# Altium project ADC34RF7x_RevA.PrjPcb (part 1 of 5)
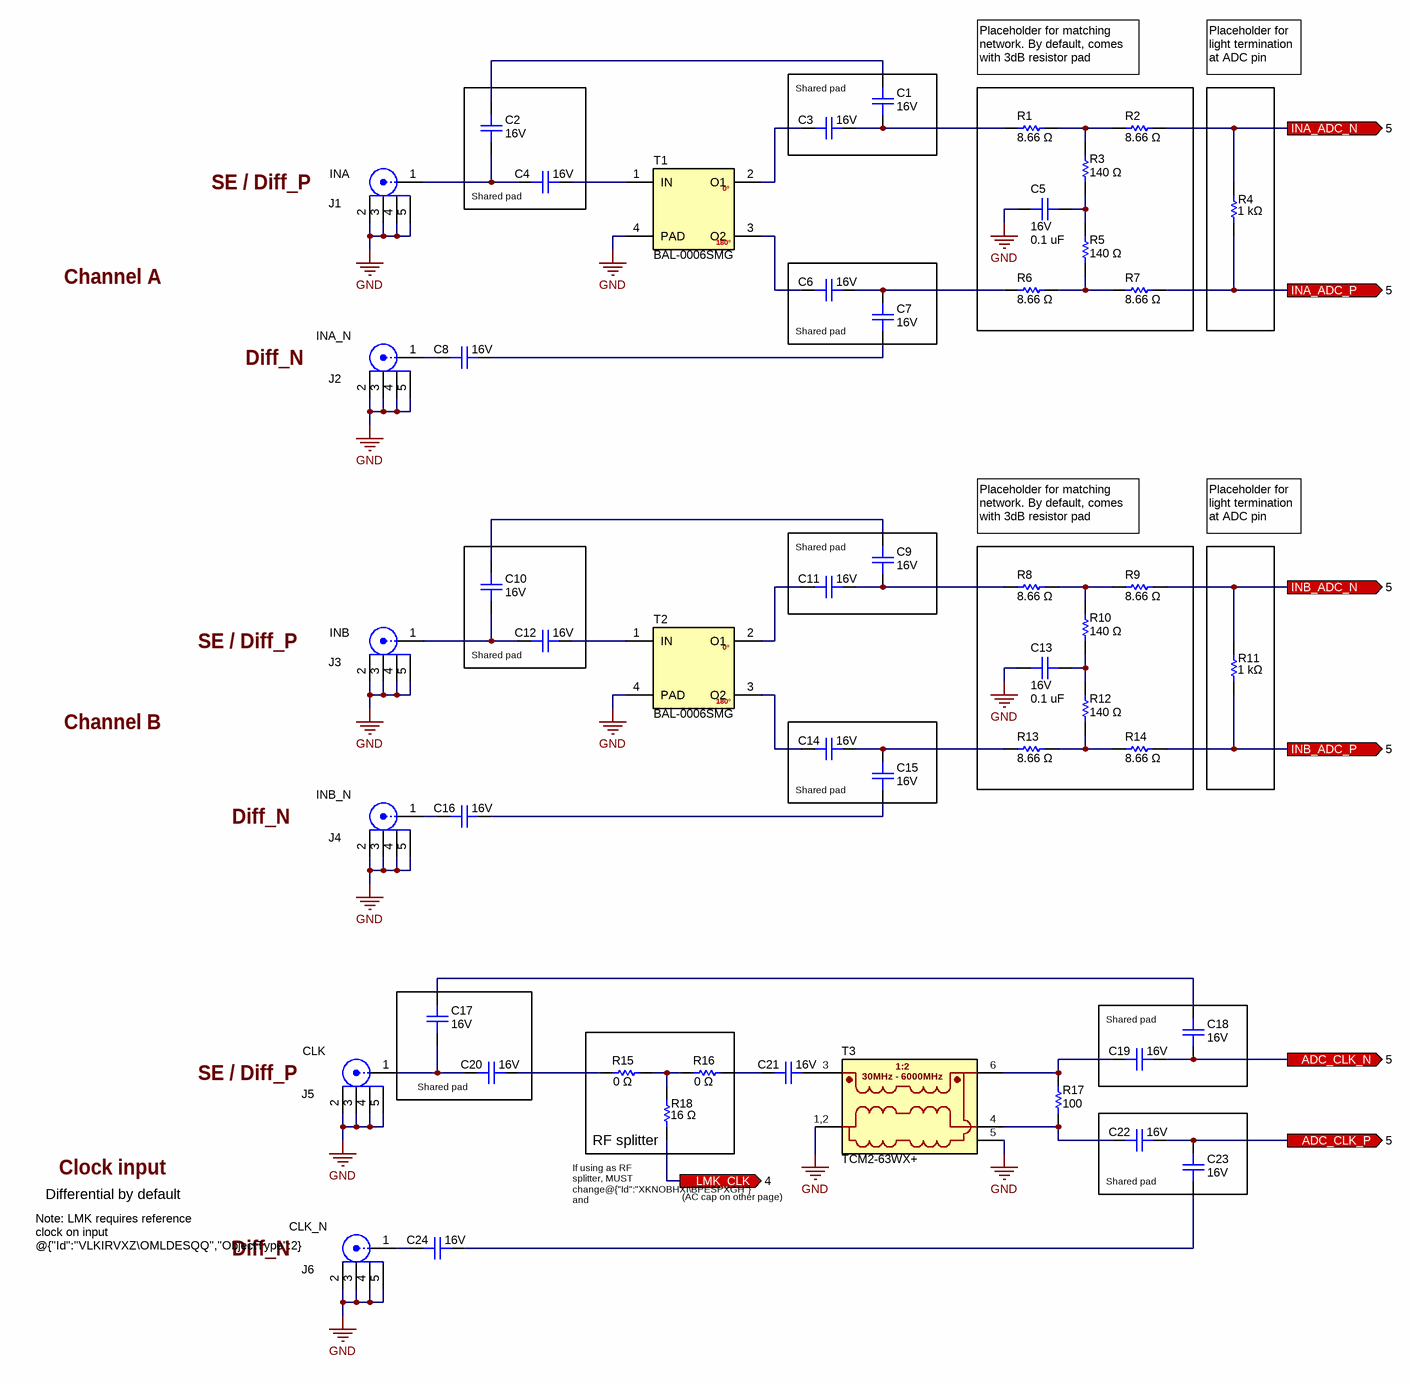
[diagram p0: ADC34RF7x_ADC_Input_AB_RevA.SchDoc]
TID: Not For Public Release; TechSupport: http://www.ti.com/support; SCH_Rev: A; PRJ_Title: ADC34RF7xEVM; PRJ_Number: -; PRJ_Engineer: CW; PRJ_Customer: Not For Public Release; PCB_Rev: A; PCB_Layout: CW/GR; EVM_Orderable: Not For Public Release; Drawn_By: CW; CopyrightYear: 2024; BrdNum: DC311
20 sheets, 672 parts. Net scope: flat (ports and power ports of the same name join across sheets).
Board file: ADC34RF7x_REV_A.PcbDoc
Sheets:
  ADC34RF7x_BlockDiagram_RevA.SchDoc
  ADC34RF7x_ADC_Input_AB_RevA.SchDoc
  ADC34RF7x_ADC_Input_CD_RevA.SchDoc
  ADC34RF7x_LMK_RevA.SchDoc
  ADC34RF7x_ADC_Dig_RevA.SchDoc
  ADC34RF7x_ADC_Power_RevA.SchDoc
  ADC34RF7x_FMC_RevA.SchDoc
  ADC34RF7x_USB_RevA.SchDoc
  ADC34RF7x_LVL_Shft_RevA.SchDoc
  ADC34RF7x_MUX_RevA.SchDoc
  ADC34RF7x_SYSREF_FPGA_MUX_RevA.SchDoc
  ADC34RF7x_Power1_RevA.SchDoc
  ADC34RF7x_Power_Sequencer.SchDoc
  ADC34RF7x_Power2_RevA.SchDoc
  ADC34RF7x_Power3_RevA.SchDoc
  ADC34RF7x_Power4_RevA.SchDoc
  ADC34RF7x_I2C_Shunts_Margining.SchDoc
  ADC34RF7x_uFit_Power.SchDoc
  ADC34RF7x_Misc_RevA.SchDoc
  ADC34RF7x_Revision History.SchDoc

## Sheet ADC34RF7x_BlockDiagram_RevA.SchDoc: Block Diagram
size 431 x 279 mm; Date: Not shown in title block; ApprovedBy: Not shown in title block; CheckedBy: Not shown in title block; Author: Not shown in title block; CompanyName: Not shown in title block; DrawnBy: CW; Engineer: Not shown in title block; Organization: Not shown in title block; Address1: Not shown in title block; Address2: Not shown in title block; Address3: Not shown in title block; Address4: Not shown in title block; DocumentNumber: 1; Revision: Use project parameter SCH_Rev; SheetNumber: 1; SheetTotal: 19; PageSetup: Record=PageOptions¦CenterHorizontal=True¦CenterVertical=True¦PrintScale=1.00¦XCorrection=1.00¦YCorrection=1.00¦PrintKind=0¦BorderSize=5000000¦LeftOffset=0¦BottomOffset=0¦Orientation=2¦PaperLength=1000¦PaperWidth=1000¦Scale=100¦PaperSource=15¦PrintQuality=600¦MediaType=1¦DitherType=10¦PaperKind=Letter¦PrintScaleMode=1

## Sheet ADC34RF7x_ADC_Input_AB_RevA.SchDoc: ADC EVM RF Input
size 431 x 279 mm; Date: Not shown in title block; ApprovedBy: Not shown in title block; CheckedBy: Not shown in title block; Author: Not shown in title block; CompanyName: Not shown in title block; DrawnBy: CW; Engineer: Not shown in title block; Organization: Not shown in title block; Address1: Not shown in title block; Address2: Not shown in title block; Address3: Not shown in title block; Address4: Not shown in title block; DocumentNumber: 2; Revision: Use project parameter SCH_Rev; SheetNumber: 2; SheetTotal: 19; PageSetup: Record=PageOptions¦CenterHorizontal=True¦CenterVertical=True¦PrintScale=1.00¦XCorrection=1.00¦YCorrection=1.00¦PrintKind=0¦BorderSize=5000000¦LeftOffset=0¦BottomOffset=0¦Orientation=2¦PaperLength=1000¦PaperWidth=1000¦Scale=100¦PaperSource=15¦PrintQuality=600¦MediaType=1¦DitherType=10¦PaperKind=Letter¦PrintScaleMode=1

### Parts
C1  Voltage - Rated: 16V  [0201_cap]  (hidden comment: 0201BB104KW160)
C2  Voltage - Rated: 16V  [0201_cap]  (hidden comment: 0201BB104KW160)
C3  Voltage - Rated: 16V  [0201_cap]  (hidden comment: 0201BB104KW160)
C4  Voltage - Rated: 16V  [0201_cap]  (hidden comment: 0201BB104KW160)
C5  value 0.1 uF  Voltage - Rated: 16V  [0201_cap]  (hidden comment: GRM033Z71C104KE14D)
C6  Voltage - Rated: 16V  [0201_cap]  (hidden comment: 0201BB104KW160)
C7  Voltage - Rated: 16V  [0201_cap]  (hidden comment: 0201BB104KW160)
C8  Voltage - Rated: 16V  [0201_cap]  (hidden comment: 0201BB104KW160)
C9  Voltage - Rated: 16V  [0201_cap]  (hidden comment: 0201BB104KW160)
C10  Voltage - Rated: 16V  [0201_cap]  (hidden comment: 0201BB104KW160)
C11  Voltage - Rated: 16V  [0201_cap]  (hidden comment: 0201BB104KW160)
C12  Voltage - Rated: 16V  [0201_cap]  (hidden comment: 0201BB104KW160)
C13  value 0.1 uF  Voltage - Rated: 16V  [0201_cap]  (hidden comment: GRM033Z71C104KE14D)
C14  Voltage - Rated: 16V  [0201_cap]  (hidden comment: 0201BB104KW160)
C15  Voltage - Rated: 16V  [0201_cap]  (hidden comment: 0201BB104KW160)
C16  Voltage - Rated: 16V  [0201_cap]  (hidden comment: 0201BB104KW160)
C17  Voltage - Rated: 16V  [0201_cap]  (hidden comment: 0201BB104KW160)
C18  Voltage - Rated: 16V  [0201_cap]  (hidden comment: 0201BB104KW160)
C19  Voltage - Rated: 16V  [0201_cap]  (hidden comment: 0201BB104KW160)
C20  Voltage - Rated: 16V  [0201_cap]  (hidden comment: 0201BB104KW160)
C21  Voltage - Rated: 16V  [0201_cap]  (hidden comment: 0201BB104KW160)
C22  Voltage - Rated: 16V  [0201_cap]  (hidden comment: 0201BB104KW160)
C23  Voltage - Rated: 16V  [0201_cap]  (hidden comment: 0201BB104KW160)
C24  Voltage - Rated: 16V  [0201_cap]  (hidden comment: 0201BB104KW160)
J1  Text1: INA  [FP-132134-15_CONN_SMA_JACK-MFG]  (hidden comment: 132134-15)
J2  Text1: INA_N  [FP-132134-15_CONN_SMA_JACK-MFG]  (hidden comment: 132134-15)
J3  Text1: INB  [FP-132134-15_CONN_SMA_JACK-MFG]  (hidden comment: 132134-15)
J4  Text1: INB_N  [FP-132134-15_CONN_SMA_JACK-MFG]  (hidden comment: 132134-15)
J5  Text1: CLK  [FP-132134-15_CONN_SMA_JACK-MFG]  (hidden comment: 132134-15)
J6  Text1: CLK_N  [FP-132134-15_CONN_SMA_JACK-MFG]  (hidden comment: 132134-15)
R1  value 8.66 Ω  [0201]  (hidden comment: RC0201FR-078R66L)
R2  value 8.66 Ω  [0201]  (hidden comment: RC0201FR-078R66L)
R3  value 140 Ω  [0201]  (hidden comment: ERJ-1GNF1400C)
R4  value 1 kΩ  [0201]  (hidden comment: ERJ-1GNF1001C)
R5  value 140 Ω  [0201]  (hidden comment: ERJ-1GNF1400C)
R6  value 8.66 Ω  [0201]  (hidden comment: RC0201FR-078R66L)
R7  value 8.66 Ω  [0201]  (hidden comment: RC0201FR-078R66L)
R8  value 8.66 Ω  [0201]  (hidden comment: RC0201FR-078R66L)
R9  value 8.66 Ω  [0201]  (hidden comment: RC0201FR-078R66L)
R10  value 140 Ω  [0201]  (hidden comment: ERJ-1GNF1400C)
R11  value 1 kΩ  [0201]  (hidden comment: ERJ-1GNF1001C)
R12  value 140 Ω  [0201]  (hidden comment: ERJ-1GNF1400C)
R13  value 8.66 Ω  [0201]  (hidden comment: RC0201FR-078R66L)
R14  value 8.66 Ω  [0201]  (hidden comment: RC0201FR-078R66L)
R15  value 0 Ω  [0201]  (hidden comment: ERJ-1GN0R00C)
R16  value 0 Ω  [0201]  (hidden comment: ERJ-1GN0R00C)
R17  ValueDisplayed: 100  [0201L]  (hidden comment: RC0201FS-7D100RL)
R18  value 16 Ω  [0201]  (hidden comment: ERJ-1GNF16R0C)
T1  BAL-0006SMG  [Marki_BAL-000xSMG]
T2  BAL-0006SMG  [Marki_BAL-000xSMG]
T3  TCM2-63WX+  [DB1627 - Vias 1,2,5]

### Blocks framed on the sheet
RF splitter: R15 R16 R18

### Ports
ADC_CLK_N (out, see 5), ADC_CLK_P (out, see 5), INA_ADC_N (out, see 5), INA_ADC_P (out, see 5), INB_ADC_N (out, see 5), INB_ADC_P (out, see 5), LMK_CLK (out, see 4)

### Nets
GND: C5.1 C13.1 J1.2 J1.3 J1.4 J1.5 J2.2 J2.3 J2.4 J2.5 J3.2 J3.3 J3.4 J3.5 J4.2 J4.3 J4.4 J4.5 J5.2 J5.3 J5.4 J5.5 J6.2 J6.3 J6.4 J6.5 T1.4(PAD) T2.4(PAD) T3.1,2(Primary) T3.5(NC)
ADC_CLK_N: C18.2 C19.2 ; port ADC_CLK_N
ADC_CLK_P: C22.2 C23.1 ; port ADC_CLK_P
INA_ADC_N: R2.2 R4.2 ; port INA_ADC_N
INA_ADC_P: R4.1 R7.2 ; port INA_ADC_P
INB_ADC_N: R9.2 R11.2 ; port INB_ADC_N
INB_ADC_P: R11.1 R14.2 ; port INB_ADC_P
LMK_CLK: R18.1 ; port LMK_CLK
NetC1_1: C1.1 C2.1
NetC1_2: C1.2 C3.2 R1.1
NetC2_2: C2.2 C4.1 J1.1
NetC3_1: C3.1 T1.2(O1)
NetC4_2: C4.2 T1.1(IN)
NetC5_2: C5.2 R3.1 R5.2
NetC6_1: C6.1 T1.3(O2)
NetC6_2: C6.2 C7.1 R6.1
NetC7_2: C7.2 C8.2
NetC8_1: C8.1 J2.1
NetC9_1: C9.1 C10.1
NetC9_2: C9.2 C11.2 R8.1
NetC10_2: C10.2 C12.1 J3.1
NetC11_1: C11.1 T2.2(O1)
NetC12_2: C12.2 T2.1(IN)
NetC13_2: C13.2 R10.1 R12.2
NetC14_1: C14.1 T2.3(O2)
NetC14_2: C14.2 C15.1 R13.1
NetC15_2: C15.2 C16.2
NetC16_1: C16.1 J4.1
NetC17_1: C17.1 C18.1
NetC17_2: C17.2 C20.1 J5.1
NetC19_1: C19.1 R17.1 T3.6(Secondary_Dot)
NetC20_2: C20.2 R15.1
NetC21_1: C21.1 R16.2
NetC21_2: C21.2 T3.3(Primary_Dot)
NetC22_1: C22.1 R17.2 T3.4(Secondary)
NetC23_2: C23.2 C24.2
NetC24_1: C24.1 J6.1
NetR1_2: R1.2 R2.1 R3.2
NetR5_1: R5.1 R6.2 R7.1
NetR8_2: R8.2 R9.1 R10.2
NetR12_1: R12.1 R13.2 R14.1
NetR15_2: R15.2 R16.1 R18.2

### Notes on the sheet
- Shared pad
- Placeholder for matching network. By default, comes with 3dB resistor pad
- Placeholder for light termination at ADC pin
- (near J1) SE / Diff_P
- (near C4) Shared pad
- Channel A
- Diff_N
- SE / Diff_P
- (near C12) Shared pad
- Channel B
- (near T3) 1:2
- (near J5) SE / Diff_P
- (near C20) Shared pad
- (near T3) 30MHz - 6000MHz
- Clock input
- Differential by default
- (AC cap on other page)
- Note: LMK requires reference clock on input @{"Id":"VLKIRVXZ\OMLDESQQ","ObjectType":2}
- (near J6) Diff_N
- (near R18) If using as RF splitter, MUST change@{"Id":"XKNOBHXI\BPESPXGH"} and @{"Id":"XKNOBHXI\NEFUFWYK"} to 16Ω

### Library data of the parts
C1-C4 C6-C12 C14-C24 = 0201RFCaps0693: Broadband Capacitors; Manufacturer: Passive Plus; Alt PartNumber: GRM033C71C104ME14D; Alt Manufacturer: Murata Electronics; Value: 0.1 uF; SizeZ_mm: 0.33; SizeY_mm: 0.3; CompType: Capactior RF; SizeX_mm: 0.58; Tolerance: ±10%; Temperature Coefficient: C0G, NP0
C5 C13 = capcc09263: CAP CER 0.1UF 16V X7R 0201; Manufacturer: Murata Electronics; CompType: Capacitor Ceramic; Tolerance: ±10%; SizeX_mm: 0.6; SizeY_mm: 0.3; SizeZ_mm: 0.33
J1-J6 = cmp00028: SMA Connector Jack, Female Socket 50Ohm Surface Mount, Through Hole Solder; Manufacturer: Amphenol RF; CompType: RF Connector
R1 R2 R6-R9 R13 R14 = RSMD020101700: Thick Film Resistors - SMD 8.66Ohms 1/20W 0201 1%; Manufacturer: Yageo; CompType: Resistor SMD; Power (Watts): 0.05W, 1/20W; Temperature Coefficient: - 100 PPM / C, + 350 PPM / C
R3 R5 R10 R12 = RSMD020100157: RES SMD 140 OHM 1% 1/20W 0201; Manufacturer: Panasonic Electronic Components; CompType: Resistor SMD; Power (Watts): 0.05W, 1/20W; Temperature Coefficient: ±200ppm/°C
R4 R11 = RSMD020100143: RES SMD 1K OHM 1% 1/20W 0201; Manufacturer: Panasonic Electronic Components; CompType: Resistor SMD; Power (Watts): 0.05W, 1/20W; Temperature Coefficient: ±200ppm/°C
R15 R16 = RSMD020101699: RES SMD 0 OHM JUMPER 1/20W 0201; Manufacturer: Panasonic Electronic Components; CompType: Resistor SMD; Power (Watts): 0.05W, 1/20W
R17 = CMP-0028070-1: RES, 100, 1%, 0.05 W, 0201; Manufacturer: Yageo America; Power_W: 50mW; TempCo: 200 ppm/C; Value_Code: 100R; U/M: EA; Value: 100; EIA_Code: E96; SizeX_mm: 0.6; SizeY_mm: 0.3; SizeZ_mm: 0.26; Value2: 0.05W; SizeArea_mm2: 0.18; CompType: Resistor; AEC Qualified: N; VDC_V: 25V; AEC Category: Q200
R18 = RSMD020100063: RES SMD 16 OHM 1% 1/20W 0201; Manufacturer: Panasonic Electronic Components; CompType: Resistor SMD; Power (Watts): 0.05W, 1/20W; Temperature Coefficient: ±200ppm/°C
T1 T2 = cmp00063: Broadband Balun, 500 kHz to 6 GHz; Manufacturer: Marki Microwave
T3 = cmp00422: 1:2 CORE & WIRE Transformer, 30 - 6000 MHz, 50Ω; Manufacturer: Mini-Circuits; CompType: Balun

## Sheet ADC34RF7x_ADC_Input_CD_RevA.SchDoc: ADC EVM RF Input
size 431 x 279 mm; Date: Not shown in title block; ApprovedBy: Not shown in title block; CheckedBy: Not shown in title block; Author: Not shown in title block; CompanyName: Not shown in title block; Engineer: Not shown in title block; Organization: Not shown in title block; Address1: Not shown in title block; Address2: Not shown in title block; Address3: Not shown in title block; Address4: Not shown in title block; DocumentNumber: 1; Revision: Use project parameter SCH_Rev; SheetNumber: 3; SheetTotal: 19; PageSetup: Record=PageOptions¦CenterHorizontal=True¦CenterVertical=True¦PrintScale=1.00¦XCorrection=1.00¦YCorrection=1.00¦PrintKind=0¦BorderSize=5000000¦LeftOffset=0¦BottomOffset=0¦Orientation=2¦PaperLength=1000¦PaperWidth=1000¦Scale=100¦PaperSource=15¦PrintQuality=600¦MediaType=1¦DitherType=10¦PaperKind=Letter¦PrintScaleMode=1
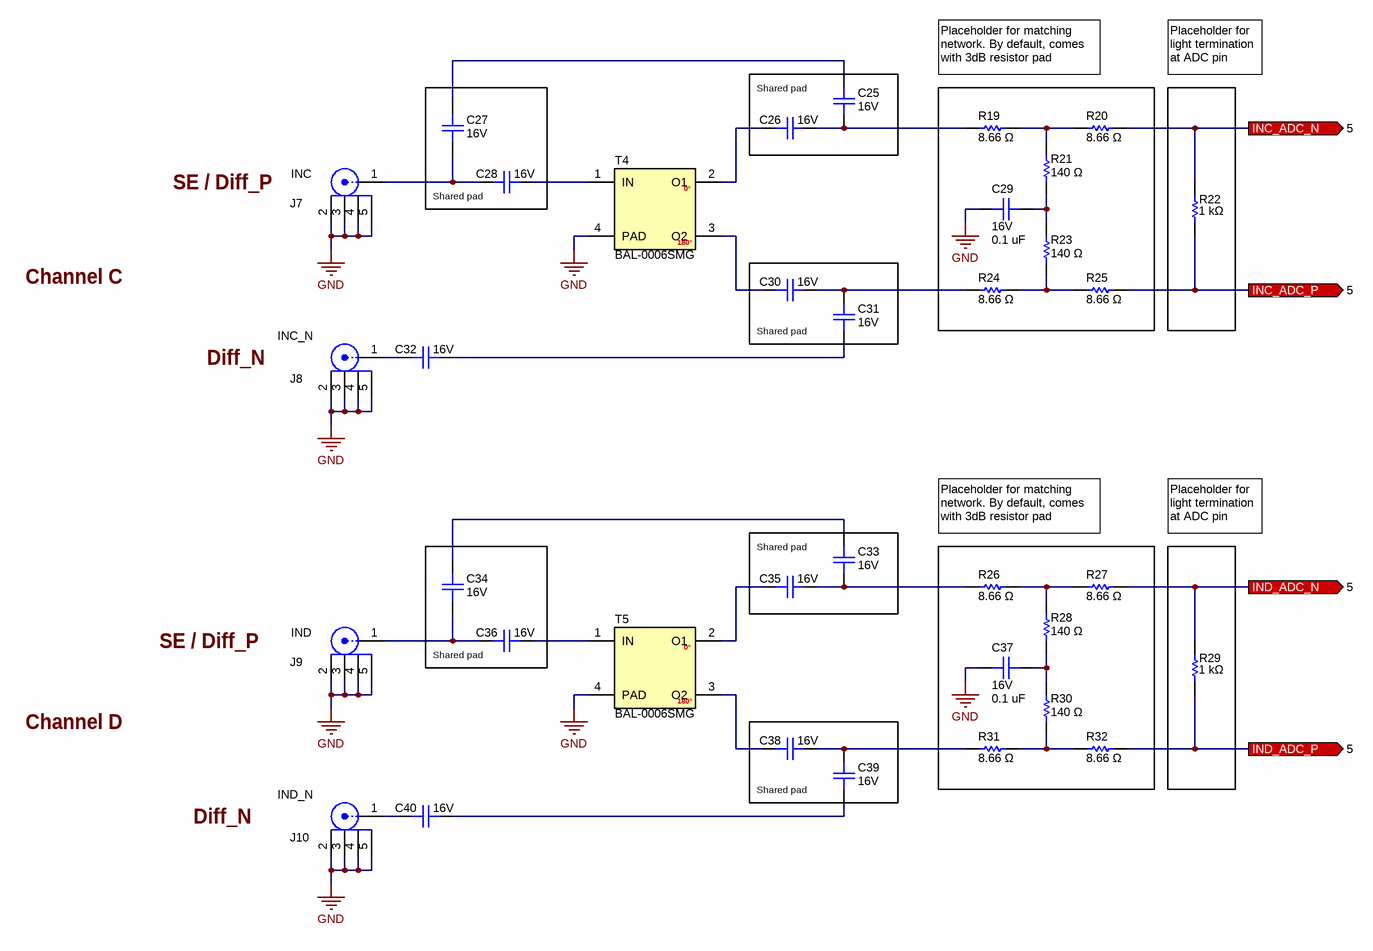
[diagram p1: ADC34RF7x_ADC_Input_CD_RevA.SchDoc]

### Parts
C25  Voltage - Rated: 16V  [0201_cap]  (hidden comment: 0201BB104KW160)
C26  Voltage - Rated: 16V  [0201_cap]  (hidden comment: 0201BB104KW160)
C27  Voltage - Rated: 16V  [0201_cap]  (hidden comment: 0201BB104KW160)
C28  Voltage - Rated: 16V  [0201_cap]  (hidden comment: 0201BB104KW160)
C29  value 0.1 uF  Voltage - Rated: 16V  [0201_cap]  (hidden comment: GRM033Z71C104KE14D)
C30  Voltage - Rated: 16V  [0201_cap]  (hidden comment: 0201BB104KW160)
C31  Voltage - Rated: 16V  [0201_cap]  (hidden comment: 0201BB104KW160)
C32  Voltage - Rated: 16V  [0201_cap]  (hidden comment: 0201BB104KW160)
C33  Voltage - Rated: 16V  [0201_cap]  (hidden comment: 0201BB104KW160)
C34  Voltage - Rated: 16V  [0201_cap]  (hidden comment: 0201BB104KW160)
C35  Voltage - Rated: 16V  [0201_cap]  (hidden comment: 0201BB104KW160)
C36  Voltage - Rated: 16V  [0201_cap]  (hidden comment: 0201BB104KW160)
C37  value 0.1 uF  Voltage - Rated: 16V  [0201_cap]  (hidden comment: GRM033Z71C104KE14D)
C38  Voltage - Rated: 16V  [0201_cap]  (hidden comment: 0201BB104KW160)
C39  Voltage - Rated: 16V  [0201_cap]  (hidden comment: 0201BB104KW160)
C40  Voltage - Rated: 16V  [0201_cap]  (hidden comment: 0201BB104KW160)
J7  Text1: INC  [FP-132134-15_CONN_SMA_JACK-MFG]  (hidden comment: 132134-15)
J8  Text1: INC_N  [FP-132134-15_CONN_SMA_JACK-MFG]  (hidden comment: 132134-15)
J9  Text1: IND  [FP-132134-15_CONN_SMA_JACK-MFG]  (hidden comment: 132134-15)
J10  Text1: IND_N  [FP-132134-15_CONN_SMA_JACK-MFG]  (hidden comment: 132134-15)
R19  value 8.66 Ω  [0201]  (hidden comment: RC0201FR-078R66L)
R20  value 8.66 Ω  [0201]  (hidden comment: RC0201FR-078R66L)
R21  value 140 Ω  [0201]  (hidden comment: ERJ-1GNF1400C)
R22  value 1 kΩ  [0201]  (hidden comment: ERJ-1GNF1001C)
R23  value 140 Ω  [0201]  (hidden comment: ERJ-1GNF1400C)
R24  value 8.66 Ω  [0201]  (hidden comment: RC0201FR-078R66L)
R25  value 8.66 Ω  [0201]  (hidden comment: RC0201FR-078R66L)
R26  value 8.66 Ω  [0201]  (hidden comment: RC0201FR-078R66L)
R27  value 8.66 Ω  [0201]  (hidden comment: RC0201FR-078R66L)
R28  value 140 Ω  [0201]  (hidden comment: ERJ-1GNF1400C)
R29  value 1 kΩ  [0201]  (hidden comment: ERJ-1GNF1001C)
R30  value 140 Ω  [0201]  (hidden comment: ERJ-1GNF1400C)
R31  value 8.66 Ω  [0201]  (hidden comment: RC0201FR-078R66L)
R32  value 8.66 Ω  [0201]  (hidden comment: RC0201FR-078R66L)
T4  BAL-0006SMG  [Marki_BAL-000xSMG]
T5  BAL-0006SMG  [Marki_BAL-000xSMG]

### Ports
INC_ADC_N (out, see 5), INC_ADC_P (out, see 5), IND_ADC_N (out, see 5), IND_ADC_P (out, see 5)

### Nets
GND: C29.1 C37.1 J7.2 J7.3 J7.4 J7.5 J8.2 J8.3 J8.4 J8.5 J9.2 J9.3 J9.4 J9.5 J10.2 J10.3 J10.4 J10.5 T4.4(PAD) T5.4(PAD)
INC_ADC_N: R20.2 R22.2 ; port INC_ADC_N
INC_ADC_P: R22.1 R25.2 ; port INC_ADC_P
IND_ADC_N: R27.2 R29.2 ; port IND_ADC_N
IND_ADC_P: R29.1 R32.2 ; port IND_ADC_P
NetC25_1: C25.1 C27.1
NetC25_2: C25.2 C26.2 R19.1
NetC26_1: C26.1 T4.2(O1)
NetC27_2: C27.2 C28.1 J7.1
NetC28_2: C28.2 T4.1(IN)
NetC29_2: C29.2 R21.1 R23.2
NetC30_1: C30.1 T4.3(O2)
NetC30_2: C30.2 C31.1 R24.1
NetC31_2: C31.2 C32.2
NetC32_1: C32.1 J8.1
NetC33_1: C33.1 C34.1
NetC33_2: C33.2 C35.2 R26.1
NetC34_2: C34.2 C36.1 J9.1
NetC35_1: C35.1 T5.2(O1)
NetC36_2: C36.2 T5.1(IN)
NetC37_2: C37.2 R28.1 R30.2
NetC38_1: C38.1 T5.3(O2)
NetC38_2: C38.2 C39.1 R31.1
NetC39_2: C39.2 C40.2
NetC40_1: C40.1 J10.1
NetR19_2: R19.2 R20.1 R21.2
NetR23_1: R23.1 R24.2 R25.1
NetR26_2: R26.2 R27.1 R28.2
NetR30_1: R30.1 R31.2 R32.1

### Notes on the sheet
- Placeholder for matching network. By default, comes with 3dB resistor pad
- Placeholder for light termination at ADC pin
- Shared pad
- (near J7) SE / Diff_P
- (near C28) Shared pad
- Channel C
- Diff_N
- SE / Diff_P
- (near C36) Shared pad
- Channel D

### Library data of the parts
C25-C28 C30-C36 C38-C40 = 0201RFCaps0693: as C1 on sheet ADC34RF7x_ADC_Input_AB_RevA
C29 C37 = capcc09263: as C5 on sheet ADC34RF7x_ADC_Input_AB_RevA
J7-J10 = cmp00028: as J1 on sheet ADC34RF7x_ADC_Input_AB_RevA
R19 R20 R24-R27 R31 R32 = RSMD020101700: as R1 on sheet ADC34RF7x_ADC_Input_AB_RevA
R21 R23 R28 R30 = RSMD020100157: as R3 on sheet ADC34RF7x_ADC_Input_AB_RevA
R22 R29 = RSMD020100143: as R4 on sheet ADC34RF7x_ADC_Input_AB_RevA
T4 T5 = cmp00063: as T1 on sheet ADC34RF7x_ADC_Input_AB_RevA

## Sheet ADC34RF7x_LMK_RevA.SchDoc: LMK04828 FPGA Clocks and SYSREF
size 431 x 279 mm; Date: Not shown in title block; ApprovedBy: Not shown in title block; CheckedBy: Not shown in title block; Author: Not shown in title block; CompanyName: Not shown in title block; DrawnBy: CW; Engineer: Not shown in title block; Organization: Not shown in title block; Address1: Not shown in title block; Address2: Not shown in title block; Address3: Not shown in title block; Address4: Not shown in title block; DocumentNumber: 9; Revision: Use project parameter SCH_Rev; SheetNumber: 4; SheetTotal: 19; PageSetup: Record=PageOptions¦CenterHorizontal=True¦CenterVertical=True¦PrintScale=1.00¦XCorrection=1.00¦YCorrection=1.00¦PrintKind=0¦BorderSize=5000000¦LeftOffset=0¦BottomOffset=0¦Orientation=2¦PaperLength=1000¦PaperWidth=1000¦Scale=100¦PaperSource=15¦PrintQuality=600¦MediaType=1¦DitherType=10¦PaperKind=Letter¦PrintScaleMode=1
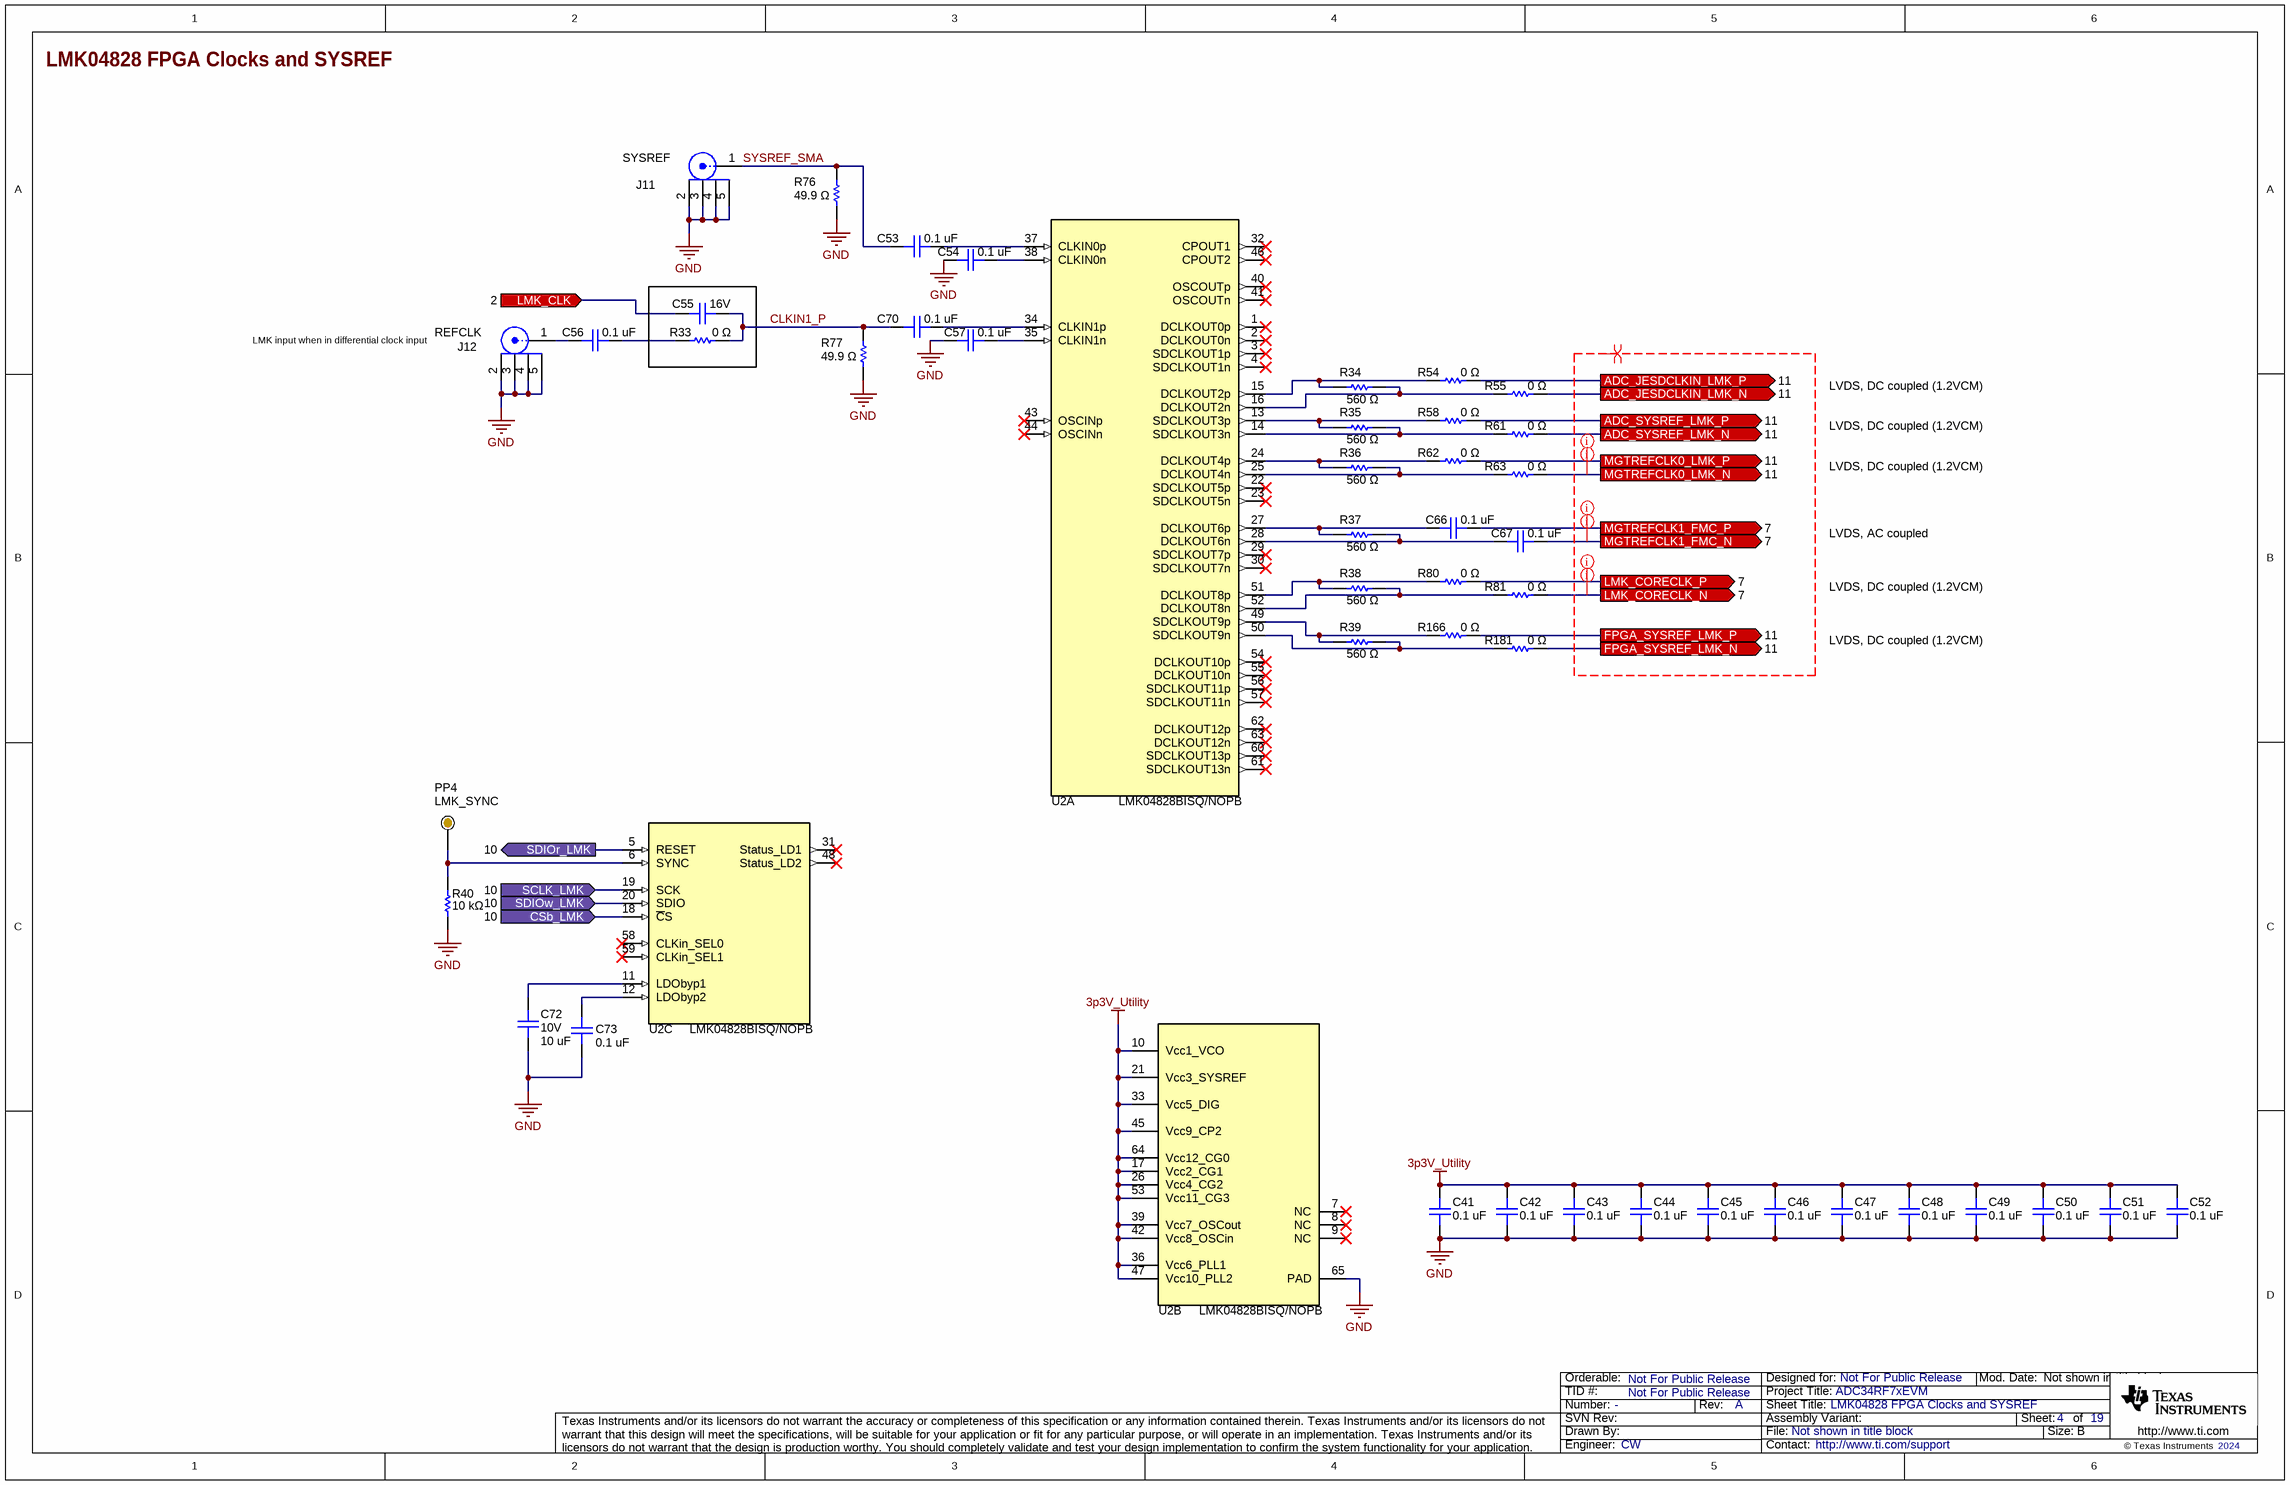
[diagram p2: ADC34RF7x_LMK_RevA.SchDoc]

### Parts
C41  value 0.1 uF  [0201_cap]  (hidden comment: C0603X5R1E104K030BB)
C42  value 0.1 uF  [0201_cap]  (hidden comment: C0603X5R1E104K030BB)
C43  value 0.1 uF  [0201_cap]  (hidden comment: C0603X5R1E104K030BB)
C44  value 0.1 uF  [0201_cap]  (hidden comment: C0603X5R1E104K030BB)
C45  value 0.1 uF  [0201_cap]  (hidden comment: C0603X5R1E104K030BB)
C46  value 0.1 uF  [0201_cap]  (hidden comment: C0603X5R1E104K030BB)
C47  value 0.1 uF  [0201_cap]  (hidden comment: C0603X5R1E104K030BB)
C48  value 0.1 uF  [0201_cap]  (hidden comment: C0603X5R1E104K030BB)
C49  value 0.1 uF  [0201_cap]  (hidden comment: C0603X5R1E104K030BB)
C50  value 0.1 uF  [0201_cap]  (hidden comment: C0603X5R1E104K030BB)
C51  value 0.1 uF  [0201_cap]  (hidden comment: C0603X5R1E104K030BB)
C52  value 0.1 uF  [0201_cap]  (hidden comment: C0603X5R1E104K030BB)
C53  value 0.1 uF  [0201_cap]  (hidden comment: C0603X5R1E104K030BB)
C54  value 0.1 uF  [0201_cap]  (hidden comment: C0603X5R1E104K030BB)
C55  Voltage - Rated: 16V  [0201_cap]  (hidden comment: 0201BB104KW160)
C56  value 0.1 uF  [0201_cap]  (hidden comment: 0201BB104KW160)
C57  value 0.1 uF  [0201_cap]  (hidden comment: C0603X5R1E104K030BB)
C66  value 0.1 uF  [0201_cap]  (hidden comment: 0201BB104KW160)
C67  value 0.1 uF  [0201_cap]  (hidden comment: 0201BB104KW160)
C70  value 0.1 uF  [0201_cap]  (hidden comment: C0603X5R1E104K030BB)
C72  value 10 uF  Voltage - Rated: 10V  [0603L_cap]  (hidden comment: 0603ZD106KAT2A)
C73  value 0.1 uF  [0201_cap]  (hidden comment: C0603X5R1E104K030BB)
J11  Text1: SYSREF  [FP-132134-15_CONN_SMA_JACK-MFG]  (hidden comment: 132134-15)
J12  Text1: REFCLK  [FP-132134-15_CONN_SMA_JACK-MFG]  (hidden comment: 132134-15)
PP4  Text1: LMK_SYNC  [ProbePoint_TH_40mil]  (hidden comment: Probe Point)  (no BOM)
R33  value 0 Ω  [0201]  (hidden comment: ERJ-1GN0R00C)
R34  value 560 Ω  [0201]  (hidden comment: ERJ-1GNF5600C)
R35  value 560 Ω  [0201]  (hidden comment: ERJ-1GNF5600C)
R36  value 560 Ω  [0201]  (hidden comment: ERJ-1GNF5600C)
R37  value 560 Ω  [0201]  (hidden comment: ERJ-1GNF5600C)
R38  value 560 Ω  [0201]  (hidden comment: ERJ-1GNF5600C)
R39  value 560 Ω  [0201]  (hidden comment: ERJ-1GNF5600C)
R40  Resistance: 10 kΩ  [0201]  (hidden comment: ERJ-1GNF1002C)
R54  value 0 Ω  [0201]  (hidden comment: ERJ-1GN0R00C)
R55  value 0 Ω  [0201]  (hidden comment: ERJ-1GN0R00C)
R58  value 0 Ω  [0201]  (hidden comment: ERJ-1GN0R00C)
R61  value 0 Ω  [0201]  (hidden comment: ERJ-1GN0R00C)
R62  value 0 Ω  [0201]  (hidden comment: ERJ-1GN0R00C)
R63  value 0 Ω  [0201]  (hidden comment: ERJ-1GN0R00C)
R76  value 49.9 Ω  [0201]  (hidden comment: ERJ-1GNF49R9C)
R77  value 49.9 Ω  [0201]  (hidden comment: ERJ-1GNF49R9C)
R80  value 0 Ω  [0201]  (hidden comment: ERJ-1GN0R00C)
R81  value 0 Ω  [0201]  (hidden comment: ERJ-1GN0R00C)
R166  value 0 Ω  [0201]  (hidden comment: ERJ-1GN0R00C)
R181  value 0 Ω  [0201]  (hidden comment: ERJ-1GN0R00C)
U2  LMK04828BISQ/NOPB  [NKD0064A]  (parts A,B,C of 3)

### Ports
ADC_JESDCLKIN_LMK_N (out, see 11), ADC_JESDCLKIN_LMK_P (out, see 11), ADC_SYSREF_LMK_N (out, see 11), ADC_SYSREF_LMK_P (out, see 11), CSb_LMK (in, see 10), FPGA_SYSREF_LMK_N (out, see 11), FPGA_SYSREF_LMK_P (out, see 11), LMK_CLK (in, see 2), LMK_CORECLK_N (out, see 7), LMK_CORECLK_P (out, see 7), MGTREFCLK0_LMK_N (out, see 11), MGTREFCLK0_LMK_P (out, see 11), MGTREFCLK1_FMC_N (out, see 7), MGTREFCLK1_FMC_P (out, see 7), SCLK_LMK (in, see 10), SDIOr_LMK (out, see 10), SDIOw_LMK (in, see 10)

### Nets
3p3V_Utility: C41.1 C42.1 C43.1 C44.1 C45.1 C46.1 C47.1 C48.1 C49.1 C50.1 C51.1 C52.1 U2.10(Vcc1_VCO) U2.17(Vcc2_CG1) U2.21(Vcc3_SYSREF) U2.26(Vcc4_CG2) U2.33(Vcc5_DIG) U2.36(Vcc6_PLL1) U2.39(Vcc7_OSCout) U2.42(Vcc8_OSCin) U2.45(Vcc9_CP2) U2.47(Vcc10_PLL2) U2.53(Vcc11_CG3) U2.64(Vcc12_CG0)
GND: C41.2 C42.2 C43.2 C44.2 C45.2 C46.2 C47.2 C48.2 C49.2 C50.2 C51.2 C52.2 C54.2 C57.1 C72.2 C73.2 J11.2 J11.3 J11.4 J11.5 J12.2 J12.3 J12.4 J12.5 R40.2 R76.1 R77.1 U2.65(PAD)
ADC_JESDCLKIN_LMK_N: R55.2 ; port ADC_JESDCLKIN_LMK_N
ADC_JESDCLKIN_LMK_P: R54.2 ; port ADC_JESDCLKIN_LMK_P
ADC_SYSREF_LMK_N: R61.2 ; port ADC_SYSREF_LMK_N
ADC_SYSREF_LMK_P: R58.2 ; port ADC_SYSREF_LMK_P
CLKIN1_P: C55.2 C70.2 R33.1 R77.2
CSb_LMK: U2.18(~{C}S) ; port CSb_LMK
FPGA_SYSREF_LMK_N: R181.2 ; port FPGA_SYSREF_LMK_N
FPGA_SYSREF_LMK_P: R166.2 ; port FPGA_SYSREF_LMK_P
LMK_CLK: C55.1 ; port LMK_CLK
LMK_CORECLK_N: R81.2 ; port LMK_CORECLK_N
LMK_CORECLK_P: R80.2 ; port LMK_CORECLK_P
MGTREFCLK0_LMK_N: R63.2 ; port MGTREFCLK0_LMK_N
MGTREFCLK0_LMK_P: R62.2 ; port MGTREFCLK0_LMK_P
MGTREFCLK1_FMC_N: C67.2 ; port MGTREFCLK1_FMC_N
MGTREFCLK1_FMC_P: C66.2 ; port MGTREFCLK1_FMC_P
SCLK_LMK: U2.19(SCK) ; port SCLK_LMK
SDIOr_LMK: U2.5(RESET) ; port SDIOr_LMK
SDIOw_LMK: U2.20(SDIO) ; port SDIOw_LMK
SYSREF_SMA: C53.2 J11.1 R76.2
NetC53_1: C53.1 U2.37(CLKIN0p)
NetC54_1: C54.1 U2.38(CLKIN0n)
NetC56_1: C56.1 R33.2
NetC56_2: C56.2 J12.1
NetC57_2: C57.2 U2.35(CLKIN1n)
NetC66_1: C66.1 R37.1 U2.27(DCLKOUT6p)
NetC67_1: C67.1 R37.2 U2.28(DCLKOUT6n)
NetC70_1: C70.1 U2.34(CLKIN1p)
NetC72_1: C72.1 U2.11(LDObyp1)
NetC73_1: C73.1 U2.12(LDObyp2)
NetPP4_1: PP4.1 R40.1 U2.6(SYNC)
NetR34_1: R34.1 R54.1 U2.15(DCLKOUT2p)
NetR34_2: R34.2 R55.1 U2.16(DCLKOUT2n)
NetR35_1: R35.1 R58.1 U2.13(SDCLKOUT3p)
NetR35_2: R35.2 R61.1 U2.14(SDCLKOUT3n)
NetR36_1: R36.1 R62.1 U2.24(DCLKOUT4p)
NetR36_2: R36.2 R63.1 U2.25(DCLKOUT4n)
NetR38_1: R38.1 R80.1 U2.51(DCLKOUT8p)
NetR38_2: R38.2 R81.1 U2.52(DCLKOUT8n)
NetR39_1: R39.1 R166.1 U2.49(SDCLKOUT9p)
NetR39_2: R39.2 R181.1 U2.50(SDCLKOUT9n)

Not connected (* = marked no-connect by the designer): U2 1(DCLKOUT0p)* 2(DCLKOUT0n)* 3(SDCLKOUT1p)* 4(SDCLKOUT1n)* 7(NC)* 8(NC)* 9(NC)* 22(SDCLKOUT5p)* 23(SDCLKOUT5n)* 29(SDCLKOUT7p)* 30(SDCLKOUT7n)* 31(Status_LD1)* 32(CPOUT1)* 40(OSCOUTp)* 41(OSCOUTn)* 43(OSCINp)* 44(OSCINn)* 46(CPOUT2)* 48(Status_LD2)* 54(DCLKOUT10p)* 55(DCLKOUT10n)* 56(SDCLKOUT11p)* 57(SDCLKOUT11n)* 58(CLKin_SEL0)* 59(CLKin_SEL1)* 60(SDCLKOUT13p)* 61(SDCLKOUT13n)* 62(DCLKOUT12p)* 63(DCLKOUT12n)*

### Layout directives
differential pair: (no net found under the mark)
net class FPGA MGT REFCLK: MGTREFCLK0_LMK_N, MGTREFCLK0_LMK_P, MGTREFCLK1_FMC_N, MGTREFCLK1_FMC_P
net class FPGA CORECLK: LMK_CORECLK_N, LMK_CORECLK_P

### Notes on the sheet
- LMK input when in differential clock input
- (near R33) Shared pad
- LVDS, DC coupled (1.2VCM)
- LVDS, AC coupled

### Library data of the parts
C41-C54 C57 C70 C73 = capcc01294: CAP CER 0.1UF 25V X5R 0201; Manufacturer: TDK Corporation; SizeZ_mm: 0.33; SizeY_mm: 0.3; CompType: Capacitor Ceramic; SizeX_mm: 0.6; Tolerance: ±10%
C55 = 0201RFCaps0693: as C1 on sheet ADC34RF7x_ADC_Input_AB_RevA
C56 C66 C67 = 0201RFCaps0693: Broadband Capacitors; Manufacturer: Passive Plus; Alt PartNumber: GRM033C71C104ME14D; Alt Manufacturer: Murata Electronics; SizeZ_mm: 0.33; SizeY_mm: 0.3; CompType: Capactior RF; SizeX_mm: 0.58; Voltage - Rated: 16V; Tolerance: ±10%; Temperature Coefficient: C0G, NP0
C72 = capcc03657: CAP CER 10UF 10V X5R 0603; Manufacturer: KYOCERA AVX; CompType: Capacitor Ceramic; Tolerance: ±10%; SizeX_mm: 1.6; SizeY_mm: 0.81; SizeZ_mm: 0.94
J11 J12 = cmp00028: as J1 on sheet ADC34RF7x_ADC_Input_AB_RevA
PP4 = Probe Point: Probe Point that can be used in lue of a test point; UniqueID: cmp00025
R33 R54 R55 R58 R61-R63 R80 R81 R166 R181 = RSMD020101699: as R15 on sheet ADC34RF7x_ADC_Input_AB_RevA
R34-R39 = RSMD020100132: RES SMD 560 OHM 1% 1/20W 0201; Manufacturer: Panasonic Electronic Components; CompType: Resistor SMD; Power (Watts): 0.05W, 1/20W; Temperature Coefficient: ±200ppm/°C
R40 = RSMD020100762: RES SMD 10K OHM 1% 1/20W 0201; Manufacturer: Panasonic Electronic Components; Value: 10 kΩ; CompType: Resistor SMD; Power (Watts): 0.05W, 1/20W; Temperature Coefficient: ±200ppm/°C
R76 R77 = RSMD020100177: RES SMD 49.9 OHM 1% 1/20W 0201; Manufacturer: Panasonic Electronic Components; CompType: Resistor SMD; Power (Watts): 0.05W, 1/20W; Temperature Coefficient: ±200ppm/°C
U2 = cmp00252: Ultra low-noise JESD204B compliant clock jitter cleaner with integrated 2370 to 2630-MHz VCO0; Manufacturer: Texas Instruments; Alt PartNumber: LMK04828BISQE/NOPB; CompType: Clocking; SizeX_mm: 9; SizeZ_mm: 0.8

## Sheet ADC34RF7x_ADC_Dig_RevA.SchDoc: ADC Input, SERDES and Digital Pins
size 431 x 279 mm; Date: Not shown in title block; ApprovedBy: Not shown in title block; CheckedBy: Not shown in title block; Author: Not shown in title block; CompanyName: Not shown in title block; DrawnBy: CW; Engineer: Not shown in title block; Organization: Not shown in title block; Address1: Not shown in title block; Address2: Not shown in title block; Address3: Not shown in title block; Address4: Not shown in title block; DocumentNumber: 3; Revision: Use project parameter SCH_Rev; SheetNumber: 5; SheetTotal: 19; PageSetup: Record=PageOptions¦CenterHorizontal=True¦CenterVertical=True¦PrintScale=1.00¦XCorrection=1.00¦YCorrection=1.00¦PrintKind=0¦BorderSize=5000000¦LeftOffset=0¦BottomOffset=0¦Orientation=2¦PaperLength=1000¦PaperWidth=1000¦Scale=100¦PaperSource=15¦PrintQuality=600¦MediaType=1¦DitherType=10¦PaperKind=Letter¦PrintScaleMode=1
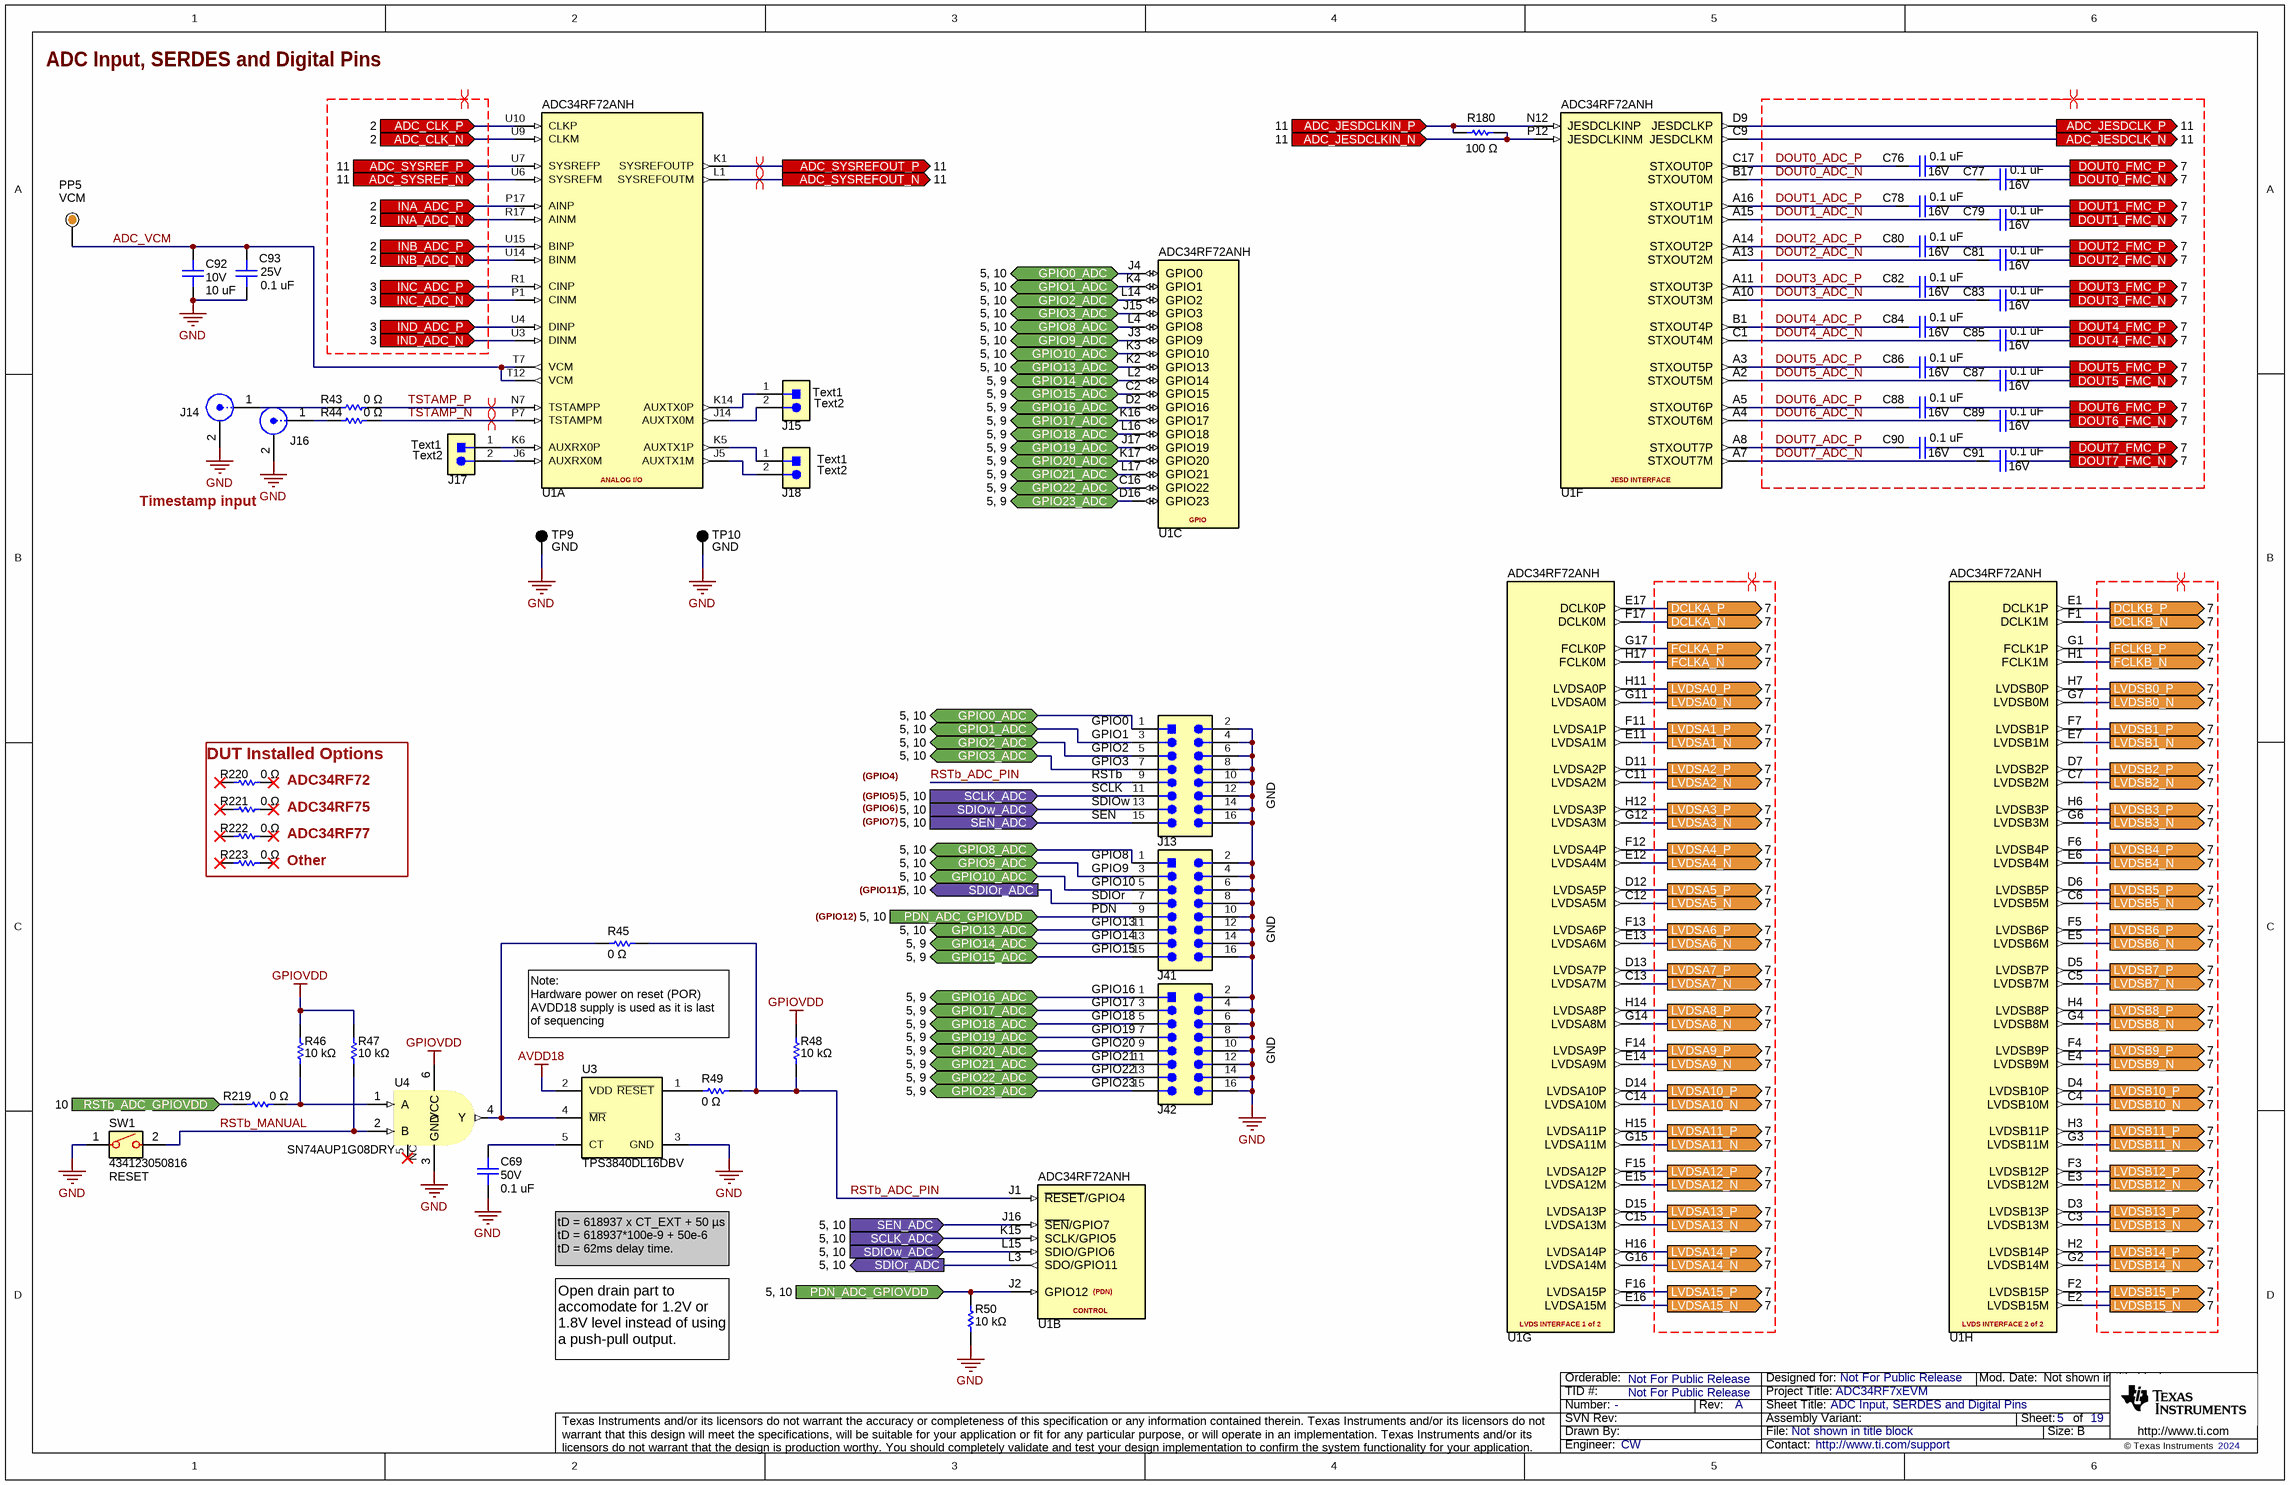
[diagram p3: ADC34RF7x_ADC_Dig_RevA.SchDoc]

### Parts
C69  value 0.1 uF  Voltage - Rated: 50V  [0402L_cap]  (hidden comment: C1005X5R1H104K050BB)
C76  value 0.1 uF  Voltage - Rated: 16V  [0201_cap]  (hidden comment: 0201BB104KW160)
C77  value 0.1 uF  Voltage - Rated: 16V  [0201_cap]  (hidden comment: 0201BB104KW160)
C78  value 0.1 uF  Voltage - Rated: 16V  [0201_cap]  (hidden comment: 0201BB104KW160)
C79  value 0.1 uF  Voltage - Rated: 16V  [0201_cap]  (hidden comment: 0201BB104KW160)
C80  value 0.1 uF  Voltage - Rated: 16V  [0201_cap]  (hidden comment: 0201BB104KW160)
C81  value 0.1 uF  Voltage - Rated: 16V  [0201_cap]  (hidden comment: 0201BB104KW160)
C82  value 0.1 uF  Voltage - Rated: 16V  [0201_cap]  (hidden comment: 0201BB104KW160)
C83  value 0.1 uF  Voltage - Rated: 16V  [0201_cap]  (hidden comment: 0201BB104KW160)
C84  value 0.1 uF  Voltage - Rated: 16V  [0201_cap]  (hidden comment: 0201BB104KW160)
C85  value 0.1 uF  Voltage - Rated: 16V  [0201_cap]  (hidden comment: 0201BB104KW160)
C86  value 0.1 uF  Voltage - Rated: 16V  [0201_cap]  (hidden comment: 0201BB104KW160)
C87  value 0.1 uF  Voltage - Rated: 16V  [0201_cap]  (hidden comment: 0201BB104KW160)
C88  value 0.1 uF  Voltage - Rated: 16V  [0201_cap]  (hidden comment: 0201BB104KW160)
C89  value 0.1 uF  Voltage - Rated: 16V  [0201_cap]  (hidden comment: 0201BB104KW160)
C90  value 0.1 uF  Voltage - Rated: 16V  [0201_cap]  (hidden comment: 0201BB104KW160)
C91  value 0.1 uF  Voltage - Rated: 16V  [0201_cap]  (hidden comment: 0201BB104KW160)
C92  value 10 uF  Voltage - Rated: 10V  [0402L_cap]  (hidden comment: 0402ZD106MAT2A)
C93  value 0.1 uF  Voltage - Rated: 25V  [0201_cap]  (hidden comment: C0603X5R1E104K030BB)
J13  Text15: SEN  Text13: SDIOw  Text11: SCLK  Text9: RSTb  Text7: GPIO3  Text5: GPIO2  Text3: GPIO1  Text2: GND  Text1: GPIO0  [HDR_8x2_TH_VT_50mil]  (hidden comment: GRPB082VWVN-RC)
J14  0853050232  [Molex_0853050232]  (value not drawn)
J15  TSW-102-14-L-S  [PBC02SAAN]  (value not drawn)
J16  0853050232  [Molex_0853050232]  (value not drawn)
J17  TSW-102-14-L-S  [PBC02SAAN]  (value not drawn)
J18  TSW-102-14-L-S  [PBC02SAAN]  (value not drawn)
J41  Text15: GPIO15  Text13: GPIO14  Text11: GPIO13  Text9: PDN  Text7: SDIOr  Text5: GPIO10  Text3: GPIO9  Text2: GND  Text1: GPIO8  [HDR_8x2_TH_VT_50mil]  (hidden comment: GRPB082VWVN-RC)
J42  Text15: GPIO23  Text13: GPIO22  Text11: GPIO21  Text9: GPIO20  Text7: GPIO19  Text5: GPIO18  Text3: GPIO17  Text2: GND  Text1: GPIO16  [HDR_8x2_TH_VT_50mil]  (hidden comment: GRPB082VWVN-RC)
PP5  Text1: VCM  [ProbePoint_TH_40mil]  (hidden comment: Probe Point)  (no BOM)
R43  value 0 Ω  [0201]  (hidden comment: ERJ-1GN0R00C)
R44  value 0 Ω  [0201]  (hidden comment: ERJ-1GN0R00C)
R45  value 0 Ω  [0201]  (hidden comment: ERJ-1GN0R00C)
R46  value 10 kΩ  [0201]  (hidden comment: ERJ-1GNF1002C)
R47  value 10 kΩ  [0201]  (hidden comment: ERJ-1GNF1002C)
R48  value 10 kΩ  [0201]  (hidden comment: ERJ-1GNF1002C)
R49  value 0 Ω  [0201]  (hidden comment: ERJ-1GN0R00C)
R50  value 10 kΩ  [0201]  (hidden comment: ERJ-1GNF1002C)
R180  value 100 Ω  [0201]  (hidden comment: ERJ-1GNF1000C)
R219  value 0 Ω  [0201]  (hidden comment: ERJ-1GN0R00C)
R220  value 0 Ω  [0805L]  (hidden comment: ERJ-6GEY0R00V)
R221  value 0 Ω  [0805L]  (hidden comment: ERJ-6GEY0R00V)
R222  value 0 Ω  [0805L]  (hidden comment: ERJ-6GEY0R00V)
R223  value 0 Ω  [0805L]  (hidden comment: ERJ-6GEY0R00V)
SW1  434123050816  Text1: RESET  [434123050816]
TP9  Text1: GND  [Keystone5001]  (hidden comment: 5001)
TP10  Text1: GND  [Keystone5001]  (hidden comment: 5001)
U1  ADC34RF72ANH  [ANH0289A]  (parts A,B,C,F,G,H of 8)
U3  TPS3840DL16DBV  [DBV0005A]
U4  SN74AUP1G08DRY  [DRY0006A]

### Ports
ADC_CLK_N (in, see 2), ADC_CLK_P (in, see 2), ADC_JESDCLK_N (out, see 11), ADC_JESDCLK_P (out, see 11), ADC_JESDCLKIN_N (in, see 11), ADC_JESDCLKIN_P (in, see 11), ADC_SYSREF_N (in, see 11), ADC_SYSREF_P (in, see 11), ADC_SYSREFOUT_N (out, see 11), ADC_SYSREFOUT_P (out, see 11), DCLKA_N (out, see 7), DCLKA_P (out, see 7), DCLKB_N (out, see 7), DCLKB_P (out, see 7), DOUT0_FMC_N (out, see 7), DOUT0_FMC_P (out, see 7), DOUT1_FMC_N (out, see 7), DOUT1_FMC_P (out, see 7), DOUT2_FMC_N (out, see 7), DOUT2_FMC_P (out, see 7), DOUT3_FMC_N (out, see 7), DOUT3_FMC_P (out, see 7), DOUT4_FMC_N (out, see 7), DOUT4_FMC_P (out, see 7), DOUT5_FMC_N (out, see 7), DOUT5_FMC_P (out, see 7), DOUT6_FMC_N (out, see 7), DOUT6_FMC_P (out, see 7), DOUT7_FMC_N (out, see 7), DOUT7_FMC_P (out, see 7), FCLKA_N (out, see 7), FCLKA_P (out, see 7), FCLKB_N (out, see 7), FCLKB_P (out, see 7), GPIO0_ADC (bidir, see 5, 10), GPIO1_ADC (bidir, see 5, 10), GPIO2_ADC (bidir, see 5, 10), GPIO3_ADC (bidir, see 5, 10), GPIO8_ADC (bidir, see 5, 10), GPIO9_ADC (bidir, see 5, 10), GPIO10_ADC (bidir, see 5, 10), GPIO13_ADC (bidir, see 5, 10), GPIO14_ADC (bidir, see 5, 9), GPIO15_ADC (bidir, see 5, 9), GPIO16_ADC (bidir, see 5, 9), GPIO17_ADC (bidir, see 5, 9), GPIO18_ADC (bidir, see 5, 9), GPIO19_ADC (bidir, see 5, 9), GPIO20_ADC (bidir, see 5, 9), GPIO21_ADC (bidir, see 5, 9), GPIO22_ADC (bidir, see 5, 9), GPIO23_ADC (bidir, see 5, 9), INA_ADC_N (in, see 2), INA_ADC_P (in, see 2), INB_ADC_N (in, see 2), INB_ADC_P (in, see 2), INC_ADC_N (in, see 3), INC_ADC_P (in, see 3), IND_ADC_N (in, see 3), IND_ADC_P (in, see 3), LVDSA0_N (out, see 7), LVDSA0_P (out, see 7), LVDSA1_N (out, see 7), LVDSA1_P (out, see 7), LVDSA2_N (out, see 7), LVDSA2_P (out, see 7), LVDSA3_N (out, see 7), LVDSA3_P (out, see 7), LVDSA4_N (out, see 7), LVDSA4_P (out, see 7), LVDSA5_N (out, see 7), LVDSA5_P (out, see 7), LVDSA6_N (out, see 7), LVDSA6_P (out, see 7), LVDSA7_N (out, see 7), LVDSA7_P (out, see 7), LVDSA8_N (out, see 7), LVDSA8_P (out, see 7), LVDSA9_N (out, see 7), LVDSA9_P (out, see 7), LVDSA10_N (out, see 7), LVDSA10_P (out, see 7), LVDSA11_N (out, see 7), LVDSA11_P (out, see 7), LVDSA12_N (out, see 7), LVDSA12_P (out, see 7), LVDSA13_N (out, see 7), LVDSA13_P (out, see 7), LVDSA14_N (out, see 7), LVDSA14_P (out, see 7), LVDSA15_N (out, see 7), LVDSA15_P (out, see 7), LVDSB0_N (out, see 7), LVDSB0_P (out, see 7), LVDSB1_N (out, see 7), LVDSB1_P (out, see 7), LVDSB2_N (out, see 7), LVDSB2_P (out, see 7), LVDSB3_N (out, see 7), LVDSB3_P (out, see 7), LVDSB4_N (out, see 7), LVDSB4_P (out, see 7), LVDSB5_N (out, see 7), LVDSB5_P (out, see 7), LVDSB6_N (out, see 7), LVDSB6_P (out, see 7), LVDSB7_N (out, see 7), LVDSB7_P (out, see 7), LVDSB8_N (out, see 7), LVDSB8_P (out, see 7), LVDSB9_N (out, see 7), LVDSB9_P (out, see 7), LVDSB10_N (out, see 7), LVDSB10_P (out, see 7), LVDSB11_N (out, see 7), LVDSB11_P (out, see 7), LVDSB12_N (out, see 7), LVDSB12_P (out, see 7), LVDSB13_N (out, see 7), LVDSB13_P (out, see 7), LVDSB14_N (out, see 7), LVDSB14_P (out, see 7), LVDSB15_N (out, see 7), LVDSB15_P (out, see 7), PDN_ADC_GPIOVDD (in, see 5, 10), RSTb_ADC_GPIOVDD (in, see 10), SCLK_ADC (in, see 5, 10), SDIOr_ADC (out, see 5, 10), SDIOw_ADC (in, see 5, 10), SEN_ADC (in, see 5, 10)

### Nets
AVDD18: U3.2(VDD)
GND: C69.1 C92.2 C93.1 J13.2 J13.4 J13.6 J13.8 J13.10 J13.12 J13.14 J13.16 J14.2 J16.2 J41.2 J41.4 J41.6 J41.8 J41.10 J41.12 J41.14 J41.16 J42.2 J42.4 J42.6 J42.8 J42.10 J42.12 J42.14 J42.16 R50.2 SW1.1 TP9.1 TP10.1 U3.3(GND) U4.3(GND)
GPIOVDD: R46.1 R47.1 R48.1 U4.6(VCC)
ADC_CLK_N: U1.U9(CLKM) ; port ADC_CLK_N
ADC_CLK_P: U1.U10(CLKP) ; port ADC_CLK_P
ADC_JESDCLK_N: U1.C9(JESDCLKM) ; port ADC_JESDCLK_N
ADC_JESDCLK_P: U1.D9(JESDCLKP) ; port ADC_JESDCLK_P
ADC_JESDCLKIN_N: R180.1 U1.P12(JESDCLKINM) ; port ADC_JESDCLKIN_N
ADC_JESDCLKIN_P: R180.2 U1.N12(JESDCLKINP) ; port ADC_JESDCLKIN_P
ADC_SYSREF_N: U1.U6(SYSREFM) ; port ADC_SYSREF_N
ADC_SYSREF_P: U1.U7(SYSREFP) ; port ADC_SYSREF_P
ADC_SYSREFOUT_N: U1.L1(SYSREFOUTM) ; port ADC_SYSREFOUT_N
ADC_SYSREFOUT_P: U1.K1(SYSREFOUTP) ; port ADC_SYSREFOUT_P
ADC_VCM: C92.1 C93.2 PP5.1 U1.T7(VCM) U1.T12(VCM)
DCLKA_N: U1.F17(DCLK0M) ; port DCLKA_N
DCLKA_P: U1.E17(DCLK0P) ; port DCLKA_P
DCLKB_N: U1.F1(DCLK1M) ; port DCLKB_N
DCLKB_P: U1.E1(DCLK1P) ; port DCLKB_P
DOUT0_ADC_N: C77.1 U1.B17(STXOUT0M)
DOUT0_ADC_P: C76.1 U1.C17(STXOUT0P)
DOUT0_FMC_N: C77.2 ; port DOUT0_FMC_N
DOUT0_FMC_P: C76.2 ; port DOUT0_FMC_P
DOUT1_ADC_N: C79.1 U1.A15(STXOUT1M)
DOUT1_ADC_P: C78.1 U1.A16(STXOUT1P)
DOUT1_FMC_N: C79.2 ; port DOUT1_FMC_N
DOUT1_FMC_P: C78.2 ; port DOUT1_FMC_P
DOUT2_ADC_N: C81.1 U1.A13(STXOUT2M)
DOUT2_ADC_P: C80.1 U1.A14(STXOUT2P)
DOUT2_FMC_N: C81.2 ; port DOUT2_FMC_N
DOUT2_FMC_P: C80.2 ; port DOUT2_FMC_P
DOUT3_ADC_N: C83.1 U1.A10(STXOUT3M)
DOUT3_ADC_P: C82.1 U1.A11(STXOUT3P)
DOUT3_FMC_N: C83.2 ; port DOUT3_FMC_N
DOUT3_FMC_P: C82.2 ; port DOUT3_FMC_P
DOUT4_ADC_N: C85.1 U1.C1(STXOUT4M)
DOUT4_ADC_P: C84.1 U1.B1(STXOUT4P)
DOUT4_FMC_N: C85.2 ; port DOUT4_FMC_N
DOUT4_FMC_P: C84.2 ; port DOUT4_FMC_P
DOUT5_ADC_N: C87.1 U1.A2(STXOUT5M)
DOUT5_ADC_P: C86.1 U1.A3(STXOUT5P)
DOUT5_FMC_N: C87.2 ; port DOUT5_FMC_N
DOUT5_FMC_P: C86.2 ; port DOUT5_FMC_P
DOUT6_ADC_N: C89.1 U1.A4(STXOUT6M)
DOUT6_ADC_P: C88.1 U1.A5(STXOUT6P)
DOUT6_FMC_N: C89.2 ; port DOUT6_FMC_N
DOUT6_FMC_P: C88.2 ; port DOUT6_FMC_P
DOUT7_ADC_N: C91.1 U1.A7(STXOUT7M)
DOUT7_ADC_P: C90.1 U1.A8(STXOUT7P)
DOUT7_FMC_N: C91.2 ; port DOUT7_FMC_N
DOUT7_FMC_P: C90.2 ; port DOUT7_FMC_P
FCLKA_N: U1.H17(FCLK0M) ; port FCLKA_N
FCLKA_P: U1.G17(FCLK0P) ; port FCLKA_P
FCLKB_N: U1.H1(FCLK1M) ; port FCLKB_N
FCLKB_P: U1.G1(FCLK1P) ; port FCLKB_P
GPIO0_ADC: J13.1 U1.J4(GPIO0) ; port GPIO0_ADC
GPIO1_ADC: J13.3 U1.K4(GPIO1) ; port GPIO1_ADC
GPIO2_ADC: J13.5 U1.L14(GPIO2) ; port GPIO2_ADC
GPIO3_ADC: J13.7 U1.J15(GPIO3) ; port GPIO3_ADC
GPIO8_ADC: J41.1 U1.L4(GPIO8) ; port GPIO8_ADC
GPIO9_ADC: J41.3 U1.J3(GPIO9) ; port GPIO9_ADC
GPIO10_ADC: J41.5 U1.K3(GPIO10) ; port GPIO10_ADC
GPIO13_ADC: J41.11 U1.K2(GPIO13) ; port GPIO13_ADC
GPIO14_ADC: J41.13 U1.L2(GPIO14) ; port GPIO14_ADC
GPIO15_ADC: J41.15 U1.C2(GPIO15) ; port GPIO15_ADC
GPIO16_ADC: J42.1 U1.D2(GPIO16) ; port GPIO16_ADC
GPIO17_ADC: J42.3 U1.K16(GPIO17) ; port GPIO17_ADC
GPIO18_ADC: J42.5 U1.L16(GPIO18) ; port GPIO18_ADC
GPIO19_ADC: J42.7 U1.J17(GPIO19) ; port GPIO19_ADC
GPIO20_ADC: J42.9 U1.K17(GPIO20) ; port GPIO20_ADC
GPIO21_ADC: J42.11 U1.L17(GPIO21) ; port GPIO21_ADC
GPIO22_ADC: J42.13 U1.C16(GPIO22) ; port GPIO22_ADC
GPIO23_ADC: J42.15 U1.D16(GPIO23) ; port GPIO23_ADC
INA_ADC_N: U1.R17(AINM) ; port INA_ADC_N
INA_ADC_P: U1.P17(AINP) ; port INA_ADC_P
INB_ADC_N: U1.U14(BINM) ; port INB_ADC_N
INB_ADC_P: U1.U15(BINP) ; port INB_ADC_P
INC_ADC_N: U1.P1(CINM) ; port INC_ADC_N
INC_ADC_P: U1.R1(CINP) ; port INC_ADC_P
IND_ADC_N: U1.U3(DINM) ; port IND_ADC_N
IND_ADC_P: U1.U4(DINP) ; port IND_ADC_P
LVDSA0_N: U1.G11(LVDSA0M) ; port LVDSA0_N
LVDSA0_P: U1.H11(LVDSA0P) ; port LVDSA0_P
LVDSA1_N: U1.E11(LVDSA1M) ; port LVDSA1_N
LVDSA1_P: U1.F11(LVDSA1P) ; port LVDSA1_P
LVDSA2_N: U1.C11(LVDSA2M) ; port LVDSA2_N
LVDSA2_P: U1.D11(LVDSA2P) ; port LVDSA2_P
LVDSA3_N: U1.G12(LVDSA3M) ; port LVDSA3_N
LVDSA3_P: U1.H12(LVDSA3P) ; port LVDSA3_P
LVDSA4_N: U1.E12(LVDSA4M) ; port LVDSA4_N
LVDSA4_P: U1.F12(LVDSA4P) ; port LVDSA4_P
LVDSA5_N: U1.C12(LVDSA5M) ; port LVDSA5_N
LVDSA5_P: U1.D12(LVDSA5P) ; port LVDSA5_P
LVDSA6_N: U1.E13(LVDSA6M) ; port LVDSA6_N
LVDSA6_P: U1.F13(LVDSA6P) ; port LVDSA6_P
LVDSA7_N: U1.C13(LVDSA7M) ; port LVDSA7_N
LVDSA7_P: U1.D13(LVDSA7P) ; port LVDSA7_P
LVDSA8_N: U1.G14(LVDSA8M) ; port LVDSA8_N
LVDSA8_P: U1.H14(LVDSA8P) ; port LVDSA8_P
LVDSA9_N: U1.E14(LVDSA9M) ; port LVDSA9_N
LVDSA9_P: U1.F14(LVDSA9P) ; port LVDSA9_P
LVDSA10_N: U1.C14(LVDSA10M) ; port LVDSA10_N
LVDSA10_P: U1.D14(LVDSA10P) ; port LVDSA10_P
LVDSA11_N: U1.G15(LVDSA11M) ; port LVDSA11_N
LVDSA11_P: U1.H15(LVDSA11P) ; port LVDSA11_P
LVDSA12_N: U1.E15(LVDSA12M) ; port LVDSA12_N
LVDSA12_P: U1.F15(LVDSA12P) ; port LVDSA12_P
LVDSA13_N: U1.C15(LVDSA13M) ; port LVDSA13_N
LVDSA13_P: U1.D15(LVDSA13P) ; port LVDSA13_P
LVDSA14_N: U1.G16(LVDSA14M) ; port LVDSA14_N
LVDSA14_P: U1.H16(LVDSA14P) ; port LVDSA14_P
LVDSA15_N: U1.E16(LVDSA15M) ; port LVDSA15_N
LVDSA15_P: U1.F16(LVDSA15P) ; port LVDSA15_P
LVDSB0_N: U1.G7(LVDSB0M) ; port LVDSB0_N
LVDSB0_P: U1.H7(LVDSB0P) ; port LVDSB0_P
LVDSB1_N: U1.E7(LVDSB1M) ; port LVDSB1_N
LVDSB1_P: U1.F7(LVDSB1P) ; port LVDSB1_P
LVDSB2_N: U1.C7(LVDSB2M) ; port LVDSB2_N
LVDSB2_P: U1.D7(LVDSB2P) ; port LVDSB2_P
LVDSB3_N: U1.G6(LVDSB3M) ; port LVDSB3_N
LVDSB3_P: U1.H6(LVDSB3P) ; port LVDSB3_P
LVDSB4_N: U1.E6(LVDSB4M) ; port LVDSB4_N
LVDSB4_P: U1.F6(LVDSB4P) ; port LVDSB4_P
LVDSB5_N: U1.C6(LVDSB5M) ; port LVDSB5_N
LVDSB5_P: U1.D6(LVDSB5P) ; port LVDSB5_P
LVDSB6_N: U1.E5(LVDSB6M) ; port LVDSB6_N
LVDSB6_P: U1.F5(LVDSB6P) ; port LVDSB6_P
LVDSB7_N: U1.C5(LVDSB7M) ; port LVDSB7_N
LVDSB7_P: U1.D5(LVDSB7P) ; port LVDSB7_P
LVDSB8_N: U1.G4(LVDSB8M) ; port LVDSB8_N
LVDSB8_P: U1.H4(LVDSB8P) ; port LVDSB8_P
LVDSB9_N: U1.E4(LVDSB9M) ; port LVDSB9_N
LVDSB9_P: U1.F4(LVDSB9P) ; port LVDSB9_P
LVDSB10_N: U1.C4(LVDSB10M) ; port LVDSB10_N
LVDSB10_P: U1.D4(LVDSB10P) ; port LVDSB10_P
LVDSB11_N: U1.G3(LVDSB11M) ; port LVDSB11_N
LVDSB11_P: U1.H3(LVDSB11P) ; port LVDSB11_P
LVDSB12_N: U1.E3(LVDSB12M) ; port LVDSB12_N
LVDSB12_P: U1.F3(LVDSB12P) ; port LVDSB12_P
LVDSB13_N: U1.C3(LVDSB13M) ; port LVDSB13_N
LVDSB13_P: U1.D3(LVDSB13P) ; port LVDSB13_P
LVDSB14_N: U1.G2(LVDSB14M) ; port LVDSB14_N
LVDSB14_P: U1.H2(LVDSB14P) ; port LVDSB14_P
LVDSB15_N: U1.E2(LVDSB15M) ; port LVDSB15_N
LVDSB15_P: U1.F2(LVDSB15P) ; port LVDSB15_P
PDN_ADC_GPIOVDD: J41.9 R50.1 U1.J2(GPIO12) ; port PDN_ADC_GPIOVDD
RSTb_ADC_GPIOVDD: R219.1 ; port RSTb_ADC_GPIOVDD
RSTb_ADC_PIN: J13.9 R45.2 R48.2 R49.2 U1.J1(~{RESET}/GPIO4)
RSTb_MANUAL: R47.2 SW1.2 U4.2(B)
SCLK_ADC: J13.11 U1.K15(SCLK/GPIO5) ; port SCLK_ADC
SDIOr_ADC: J41.7 U1.L3(SDO/GPIO11) ; port SDIOr_ADC
SDIOw_ADC: J13.13 U1.L15(SDIO/GPIO6) ; port SDIOw_ADC
SEN_ADC: J13.15 U1.J16(~{SEN}/GPIO7) ; port SEN_ADC
TSTAMP_N: R44.1 U1.P7(TSTAMPM)
TSTAMP_P: R43.1 U1.N7(TSTAMPP)
NetC69_2: C69.2 U3.5(CT)
NetJ14_1: J14.1 R43.2
NetJ15_1: J15.1 U1.K14(AUXTX0P)
NetJ15_2: J15.2 U1.J14(AUXTX0M)
NetJ16_1: J16.1 R44.2
NetJ17_1: J17.1 U1.K6(AUXRX0P)
NetJ17_2: J17.2 U1.J6(AUXRX0M)
NetJ18_1: J18.1 U1.K5(AUXTX1P)
NetJ18_2: J18.2 U1.J5(AUXTX1M)
NetR45_1: R45.1 U3.4(~{MR}) U4.4(Y)
NetR46_2: R46.2 R219.2 U4.1(A)
NetR49_1: R49.1 U3.1(~{RESET})

Not connected (* = marked no-connect by the designer): R220 1* 2*; R221 1* 2*; R222 1* 2*; R223 1* 2*; U4 5(NC)*

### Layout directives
differential pair; net class SERDES_DP: DOUT0_ADC_N, DOUT0_ADC_P, DOUT1_ADC_N, DOUT1_ADC_P, DOUT2_ADC_N, DOUT2_ADC_P, DOUT3_ADC_N, DOUT3_ADC_P, DOUT4_ADC_N, DOUT4_ADC_P, DOUT5_ADC_N, DOUT5_ADC_P, DOUT6_ADC_N, DOUT6_ADC_P, DOUT7_ADC_N, DOUT7_ADC_P
differential pair: (no net found under the mark), ADC_SYSREFOUT_N, ADC_SYSREFOUT_P, TSTAMP_N, TSTAMP_P
differential pair; net class LVDS_B: (no net found under the mark)
differential pair; net class LVDS_A: (no net found under the mark)

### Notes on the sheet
- Timestamp input
- ADC34RF77
- ADC34RF72
- ADC34RF75
- (GPIO5)
- (GPIO6)
- (GPIO7)
- (GPIO4)
- DUT Installed Options
- Other
- (GPIO11)
- (GPIO12)
- (near R45) Note:
  Hardware power on reset (POR)
  AVDD18 supply is used as it is last of sequencing
- tD = 618937 x CT_EXT + 50 µs
  tD = 618937*100e-9 + 50e-6
  tD = 62ms delay time.
- Open drain part to accomodate for 1.2V or 1.8V level instead of using a push-pull output.

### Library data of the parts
C69 = capcc01268: CAP CER 0.1UF 50V X5R 0402; Manufacturer: TDK Corporation; CompType: Capacitor Ceramic; Tolerance: ±10%; SizeX_mm: 1; SizeY_mm: 0.5; SizeZ_mm: 0.55
C76-C91 = 0201RFCaps0693: Broadband Capacitors; Manufacturer: Passive Plus; Alt PartNumber: GRM033C71C104ME14D; Alt Manufacturer: Murata Electronics; SizeZ_mm: 0.33; SizeY_mm: 0.3; CompType: Capactior RF; SizeX_mm: 0.58; Tolerance: ±10%; Temperature Coefficient: C0G, NP0
C92 = capcc09406: CAP CER 10UF 10V X5R 0402; Manufacturer: KYOCERA AVX; CompType: Capacitor Ceramic; Tolerance: ±20%; SizeX_mm: 1; SizeY_mm: 0.5; SizeZ_mm: 0.7
C93 = capcc01294: as C41 on sheet ADC34RF7x_LMK_RevA
J13 J41 J42 = GRPB082VWVN-RC: Header, 50mil, 8x2, Gold, TH; Manufacturer: Sullins Connector Solutions; Pitch (mm): 1.27
J14 J16 = cmp00032: SMP Connector Plug, Male Pin 50Ohm Surface Mount Solder; Manufacturer: Molex; SymbolCreator: a0799628; Cert_UL: Y; ContactFinish: Gold; CompType: RF Connector; CT: False; Voltage_V: 335V
J15 J17 J18 = TSW-102-14-L-S: Header, 100mil, 2x1, Gold, TH; Manufacturer: Samtec; Alt Manufacturer: Sullins Connector Solutions; UniqueID: cmp00014; Pitch (mm): 2.54
PP5 = Probe Point: as PP4 on sheet ADC34RF7x_LMK_RevA
R43-R45 R49 R219 = RSMD020101699: as R15 on sheet ADC34RF7x_ADC_Input_AB_RevA
R46-R48 R50 = RSMD020100762: RES SMD 10K OHM 1% 1/20W 0201; Manufacturer: Panasonic Electronic Components; CompType: Resistor SMD; Power (Watts): 0.05W, 1/20W; Temperature Coefficient: ±200ppm/°C
R180 = RSMD020100289: RES SMD 100 OHM 1% 1/20W 0201; Manufacturer: Panasonic Electronic Components; CompType: Resistor SMD; Power (Watts): 0.05W, 1/20W; Temperature Coefficient: ±200ppm/°C
R220-R223 = RSMD080510615: RES SMD 0 OHM JUMPER 1/8W 0805; Manufacturer: Panasonic Electronic Components; CompType: Resistor SMD; Power (Watts): 0.125W, 1/8W; SizeX_mm: 2; SizeY_mm: 1.25; SizeZ_mm: 0.7
SW1 = cmp00291: SWITCH TACTILE SPST-NO 0.05A 12V; Manufacturer: Würth Elektronik; CompType: Push Button; SizeX_mm: 3; SizeY_mm: 3.5
TP9 TP10 = cmp00051: Test Point, Miniature, Black TH; Manufacturer: Keystone
U1 = ADC34RF72ANH: Quad channel 16-bit 1.5 GSPS RF sampling data converter, FCCSP-289 (ANH0289A); Alternate Manufacturer: Texas Instruments; SizeX_mm: 14; CompType: IC; SizeZ_mm: 1.9; SizeArea_mm2: 196; AEC Qualified: N
U3 = TPS3840DL16DBV: Open Drain, 1.6V threshold, Nano Power, Wide VIN Voltage Detector with Programmable Delay; Manufacturer: Texas Instruments
U4 = cmp00518: Low-Power Single 2-Input Positive-AND Gate; PartNumber: SN74AUP1G08DRYR; Manufacturer: Texas Instruments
